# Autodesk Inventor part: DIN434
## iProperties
Shininess: 64.0
Length Units: 11269
Angle Units: 11279
Time Units: 11290
Mass Units: 11283
Length Display Precision: 3
Angle Display Precision: 2
Compacted: True
Created: 2003-04
Part Number: DIN434
Material: St.
Document SubType Name: Modeling
Designer: Robbert Osinga
Description: SqrTaperwasher M16 U8%
Density: 0.0
Volumn: 0.0
Area: 0.0
PropertySet Name: Model Information
Control State: 0
Master: False
Checked Out: False
Checked Out By: ?
Author: Robbert Osinga
Revision Number: 0
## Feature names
1. Extrusion2
2. Hole1
3. Chamfer1
4. Extrusion4
5. Extrusion5
